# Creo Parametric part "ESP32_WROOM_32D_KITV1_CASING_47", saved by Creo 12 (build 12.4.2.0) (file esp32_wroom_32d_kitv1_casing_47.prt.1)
Units: Custom; MM, KILOGRAM, SECS

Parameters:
  PTC_WM_ITERATION = "0"
  PTC_WM_VERSION = "-.0"
  PTC_WM_LIFECYCLE_STATE = "In Work"
  PTC_WM_LIFECYCLE = "MO_CADDocument"
  PTC_WM_CREATED_BY = "Maximilian Roepper (Z0017RMS: MO)"
  PTC_WM_CREATED_ON = "18-Sep-26 11:36:42 AM"
  PTC_WM_MODIFIED_BY = "Maximilian Roepper (Z0017RMS: MO)"
  PTC_WM_MODIFIED_ON = "18-Sep-26 11:36:46 AM"
  PDMLINKNUMBER = "PDM000071454870"
  PTC_WM_NAME = "esp32_wroom_32d_kitv1_casing_47.prt"
  PTC_WM_NUMBER = "PDM000071454870"

Other parameters: WEIGHT, WEIGHT_FACTOR, WEIGHT_ADD, _MASS_TEMP, _DIFF_TEMP, MC_ERRORS, SUPPLIER

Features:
  1. coordinate system
  2. datum plane "PRT_YZ"
  3. datum plane "PRT_XY"
  4. datum plane "PRT_XZ"
  5. coordinate system
  6. datum axis
  7. datum axis
  8. datum axis
  9. coordinate system
  10. imported feature
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
Other named items: PRT, SIEMENS_MO, DRW_VIEW_ORG, PRT_X, PRT_Y, PRT_Z, CS0, ROUGH_GROB

Layers: 00_STD_CSYS-KSYS, 01_STD_PLANES-EBENEN, 02_STD_AXES-ACHSEN, 03_STD_CSYS-KSYS, 24_IMPORT_FEAT-IMPORT_KE

Surfaces: 6 plane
